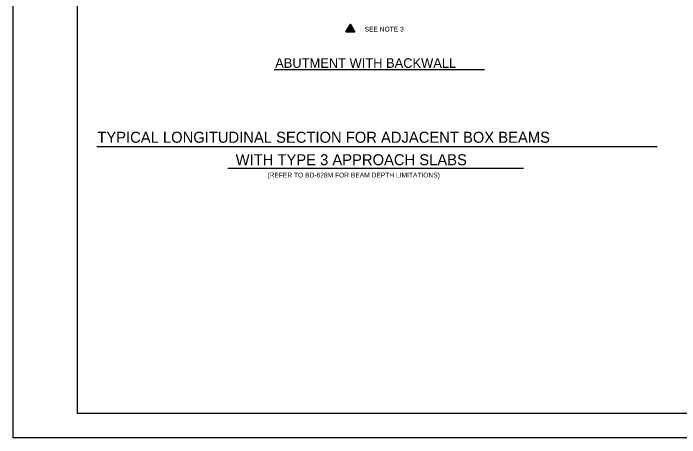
# Model space of a CAD drawing. Extents: x 638653 to 642302, y 298557 to 300414.
# Drawn here: x 638982.2 to 639397.3, y 298556.5 to 298821.1 of the extents above; entities that cross this region are included whole.
import ezdxf

# ---------------------------------------------------------------- set-up
doc = ezdxf.new("R2010")
doc.units = 0
doc.layers.add('1', color=7, linetype='Continuous')
doc.layers.add('PLT-BNDY', color=7, linetype='Continuous')

msp = doc.modelspace()

# ---------------------------------------------------------------- linework, layer by layer
at = {"layer": '1'}
for p, q in [((639022.16, 298571.52), (639022.16, 299135.52)), ((639192.22, 298811.24), (639192.22, 298811.24)), ((639275.82, 298785.83), (639144.64, 298785.83)), ((639383.4, 298737.8), (639034.22, 298737.8)), ((639300.08, 298724.36), (639115.83, 298724.36)), ((639808.16, 298571.52), (639022.16, 298571.52)), ((638982.16, 298556.52), (638982.16, 298556.52))]:
    msp.add_line(p, q, dxfattribs=at)
for points in [[(639189.43, 298809.63), (639195.01, 298809.63), (639192.22, 298814.46), (639189.43, 298809.63)], [(639189.43, 298809.63), (639192.22, 298814.46), (639195.01, 298809.63), (639189.43, 298809.63), (639192.21, 298814.32), (639194.92, 298809.69), (639189.54, 298809.68), (639192.23, 298814.17), (639194.81, 298809.76), (639189.67, 298809.74), (639192.23, 298814.03), (639194.68, 298809.85), (639189.79, 298809.81), (639192.23, 298813.88), (639194.57, 298809.91), (639189.93, 298809.9), (639192.23, 298813.72), (639194.43, 298809.98), (639190.08, 298809.98), (639192.23, 298813.54), (639194.3, 298810.06), (639190.21, 298810.06), (639192.22, 298813.38), (639194.16, 298810.15), (639190.34, 298810.14), (639192.22, 298813.22), (639194.01, 298810.24), (639190.48, 298810.21), (639192.24, 298813.06), (639193.84, 298810.31), (639190.62, 298810.29), (639192.24, 298812.9), (639193.67, 298810.42), (639190.77, 298810.37), (639192.24, 298812.71), (639193.53, 298810.52), (639190.91, 298810.45), (639192.23, 298812.55), (639193.38, 298810.61), (639191.08, 298810.54), (639192.24, 298812.38), (639193.24, 298810.68), (639191.24, 298810.61), (639192.23, 298812.2), (639193.08, 298810.77), (639191.42, 298810.7), (639192.23, 298812.04), (639192.91, 298810.86), (639191.55, 298810.78), (639192.23, 298811.88), (639192.75, 298810.95), (639191.71, 298810.86), (639192.23, 298811.72), (639192.62, 298811.01), (639191.84, 298810.93), (639192.23, 298811.56), (639192.5, 298811.08), (639191.97, 298811), (639192.23, 298811.41), (639192.39, 298811.14), (639192.11, 298811.1), (639192.23, 298811.23), (639195, 298809.64), (639192.23, 298811.23), (639192.23, 298814.42), (639192.23, 298811.22), (639189.44, 298809.64)]]:
    msp.add_lwpolyline(points, dxfattribs=at)
at = {"layer": 'PLT-BNDY'}
msp.add_lwpolyline([(638982.16, 299150.52), (639823.16, 299150.52), (639823.16, 298556.52), (638982.16, 298556.52)], close=True, dxfattribs=at)

# ---------------------------------------------------------------- texts
at = {"layer": '1'}
for s, height, p in [('SEE NOTE 3', 3, (639201.04, 298809.76)), ('ABUTMENT WITH BACKWALL', 6, (639145.32, 298787.13)), ('TYPICAL LONGITUDINAL SECTION FOR ADJACENT BOX BEAMS', 6.8753, (639034.51, 298740.42)), ('WITH TYPE 3 APPROACH SLABS', 6.8753, (639120.69, 298726.41)), ('(REFER TO BD-628M FOR BEAM DEPTH LIMITATIONS)', 3, (639140.48, 298718.79))]:
    msp.add_text(s, height=height, dxfattribs=at).set_placement(p)

doc.saveas('drawing.dxf')
